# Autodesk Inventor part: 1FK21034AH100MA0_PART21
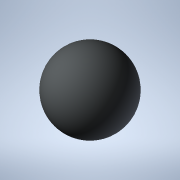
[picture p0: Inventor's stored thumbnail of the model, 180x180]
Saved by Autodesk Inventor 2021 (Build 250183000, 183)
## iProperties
Created: 2025-04
Part Number: 1FK21034AH100MA0_PART21
Material: Generic
Catalog Web Link: www.3dfindit.com
Description: -Servo synchronous motor
Document SubType Name: Modeling
Designer: psAdmin
Mass: 0.113097 g
Surface Area: 1.13097 cm^2
Volume: 0.113097 cm^3
Density: 1 g/cm^3
Appearance: PSOLRGB-212-217-219
Category: PARTsolutions
Title: 1FK21034AH100MA0_PART21
Author: Cadenas PARTsolutions
Comments: Servo synchronous motor
Sending System: PARTsolutions
Preprocessor: ST-DEVELOPER v19.3
PSOL_IDENT_0: {$CADENAS_DATA/23d-libs/siemens_ag/_cat_/39/97/1fk21034ah100ma0.prj},216 {VTYP=3D},{NB=1FK21034AH100
PSOL_IDENT_1: MA0_PART21},{LINA=1FK21034AH100MA0_PART21},{NN=1FK21034AH100MA0_PART21},{NOPRJ=TRUE},{DATE=19.08.202
PSOL_IDENT_2: 5 14:00:33},{GEOMDATE=30.07.2025 02:02:21},{VERSION=},{LINEID=10},{WBVAR=},{WBNUMERIC=}  {NB=1FK2103
PSOL_IDENT_3: 4AH100MA0_PART21},{LINA=1FK21034AH100MA0_PART21},{KT=DUMMY},{PREVIEW=../../../_pool_/d3/78/p_d211_xx
PSOL_IDENT_4: _00934j.png},{DESCSHORT=SIMOTICS S-1FK2 HD, SINAMICS S210 3AC 400V-480V, 1.01 Nm, 4500 rpm},{DESCLON
PSOL_IDENT_5: G=SIMOTICS S-1FK2 HD servo motor M0=1.27 Nm; PN = 0.48 kW at nN=4500 rpm (380-480 V); PN = 0.3 kW at
PSOL_IDENT_6: nN=2500 rpm (200-240 V); with holding brake; degree of protection IP64; cylindrical shaft D14 x 30
PSOL_IDENT_7: mm; absolute encoder 22-bit + 12-bit multiturn (encoder AM22DQC); with OCC interface; plug size M17,
PSOL_IDENT_8: rotatable; SIMOTICS S-1FK2 servomotorfor a wide range of uses in industrial environments. SIMOTICS
PSOL_IDENT_9: S‑1FK2 servomotors are compact synchronous motors with a high dynamic performance that set themselve
PSOL_IDENT_10: s apart as a result of their high power density, degree of protection and overload capability. The m
PSOL_IDENT_11: otors are available in two variants: as High Dynamic variant (highest dynamic performance as a resul
PSOL_IDENT_12: t of the low intrinsic moment of inertia for applications demanding a high dynamic performance with
PSOL_IDENT_13: low moved masses) - and as Compact variant (precise and stable closed-loop control for medium up to
PSOL_IDENT_14: large moved masses as a result of a medium intrinsic moment of inertia). SIMOTICSS‑1FK2 servomotors
PSOL_IDENT_15: fully exploit their strengths in a system with the SINAMICSS210 frequency converter and simple conne
PSOL_IDENT_16: ction using the one cable connection (OCC). Advantages include the short control and positioning tim
PSOL_IDENT_17: es, fast and precise correction of disturbing quantities as well as stable control with a high dynam
PSOL_IDENT_18: ic performance. The servo motors can be configured to address a wide range of requirements. For exam
PSOL_IDENT_19: ple with and without holding brake, IP64 or IP65 degree of protection, singleturn or multiturn absol
PSOL_IDENT_20: ute encoders - to name just a few. Further, the servomotors are available in different shaft heights
PSOL_IDENT_21: extending from 20 to 100. A shaft sealing ring is available to achieve an IP65 degree of protection
PSOL_IDENT_22: and for subsequent mounting at the motor or as spare part. SIMOTICS - the optimum motor for each an
PSOL_IDENT_23: d every motion control application.},{INTNO=195125454019},{SUPPLIERALTNO=1FK2103-4AH10-0MA0},{MANUID=
PSOL_IDENT_24: 1FK21034AH100MA0},{MANUNAME=Siemens},{MANUTYPEDESC=SYNCHRONOUS MOTOR 1FK2 HD 1,27 NM},{AAU732=SIMOTI
PSOL_IDENT_25: CS},{AAO057=S-1FK2},{AAU734=SIMOTICS S-1FK2 HD servo motor M0=1.27 Nm; PN = 0.48 kW at nN=4500 rpm (
PSOL_IDENT_26: 380-480 V); PN = 0.3 kW at nN=2500 rpm (200-240 V); with holding brake; degree of protection IP64; c
PSOL_IDENT_27: ylindrical shaft D14 x 30 mm; absolute encoder 22-bit + 12-bit multiturn (encoder AM22DQC); with OCC
PSOL_IDENT_28: interface; plug size M17, rotatable;},{AAW338=SYNCHRONOUS MOTOR 1FK2 HD 1,27 NM},{AAO742=SIMOTICS},
PSOL_IDENT_29: {AAO663=4034106444921},{NOCUPEROU=1},{PRICEQUANTITY=1},{QUANTITYMIN=1},{QUANTITYINT=1},{CTN=85015100
PSOL_IDENT_30: },{COO=RO},{AAO676=1FK2103-4AH10-0MA0},{AAO677=Siemens AG},{ORDERUNIT=C62},{CONTENTUNIT=C62}
NB: 1FK21034AH100MA0_PART21
NT: Servo synchronous motor
NBSYN: $MANUID._PART21
LINA: 1FK21034AH100MA0_PART21
CATALOG: SIEMENS
PREVIEW: ../../../_pool_/d3/78/p_d211_xx_00934j.png
DESCSHORT: SIMOTICS S-1FK2 HD, SINAMICS S210 3AC 400V-480V, 1.01 Nm, 4500 rpm
DESCLONG: SIMOTICS S-1FK2 HD servo motor M0=1.27 Nm; PN = 0.48 kW at nN=4500 rpm (380-480 V); PN = 0.3 kW at nN=2500 rpm (200-240 V); with holding brake; degree of protec
INTNO: 195125454019
SUPPLIERALTNO: 1FK2103-4AH10-0MA0
MANUID: 1FK21034AH100MA0
MANUNAME: Siemens
MANUTYPEDESC: SYNCHRONOUS MOTOR 1FK2 HD 1,27 NM
AAU732: SIMOTICS
AAO057: S-1FK2
AAU734: SIMOTICS S-1FK2 HD servo motor M0=1.27 Nm; PN = 0.48 kW at nN=4500 rpm (380-480 V); PN = 0.3 kW at nN=2500 rpm (200-240 V); with holding brake; degree of protec
AAW338: SYNCHRONOUS MOTOR 1FK2 HD 1,27 NM
AAO742: SIMOTICS
AAO663: 4034106444921.0
NOCUPEROU: 1
PRICEQUANTITY: 1
QUANTITYMIN: 1
QUANTITYINT: 1
CTN: 85015100
COO: RO
ARTICLENO: 1FK21034AH100MA0_PART21
BOMINFO: 1FK21034AH100MA0_PART21
CREATOR: CADENAS GmbH
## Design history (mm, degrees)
feature "2025_04_17_15_09_00_0361"
body "Solid1"
